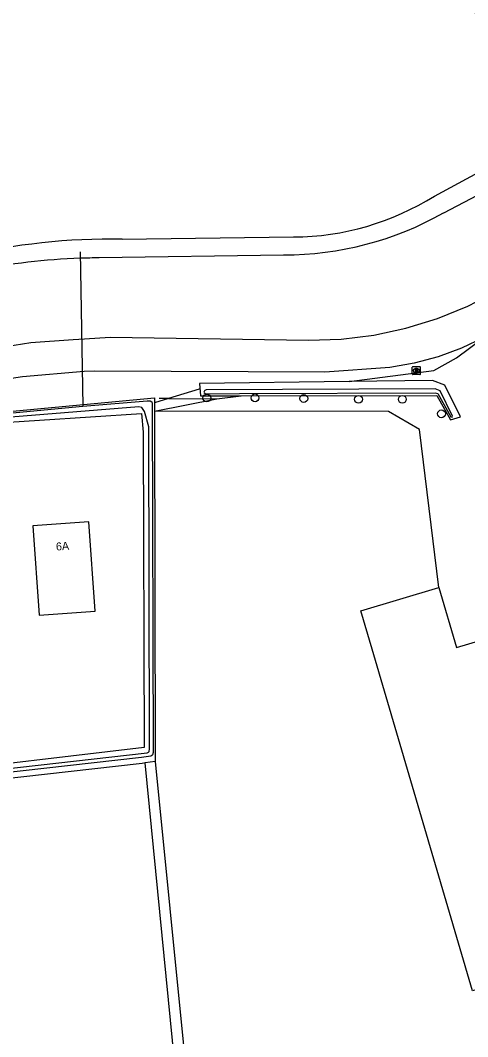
# Model space of a CAD drawing. Extents: x 161389 to 162585, y 388479 to 389761.
# Drawn here: x 162428.4 to 162484.3, y 389499.2 to 389626.2 of the extents above; entities that cross this region are included whole.
import ezdxf

# ---------------------------------------------------------------- set-up
doc = ezdxf.new("R2010")
doc.units = 0
for name, color, linetype in [('IMGEO_Boom', 7, 'Continuous'), ('IMGEO_Bouwland', 7, 'Continuous'), ('IMGEO_Duiker', 7, 'Continuous'), ('IMGEO_Erf', 7, 'Continuous'), ('IMGEO_Grasland_agrarisch', 7, 'Continuous'), ('IMGEO_Groenvoorziening', 7, 'Continuous'), ('IMGEO_Hek', 7, 'Continuous'), ('IMGEO_Pand', 7, 'Continuous'), ('IMGEO_Pand_nummerreeks', 7, 'Continuous'), ('IMGEO_Rijbaan_lokaal_gesloten', 7, 'Continuous'), ('IMGEO_Rioolput', 7, 'Continuous'), ('IMGEO_Waterloop', 7, 'Continuous')]:
    doc.layers.add(name, color=color, linetype=linetype)

msp = doc.modelspace()

# ---------------------------------------------------------------- linework, layer by layer
at = {"layer": 'IMGEO_Boom'}
for centre in [(162451.68, 389579.01), (162457.71, 389579.03), (162463.8, 389578.95), (162470.64, 389578.85), (162476.12, 389578.85), (162481, 389577.04)]:
    msp.add_circle(centre, 0.489, dxfattribs=at)
at = {"layer": 'IMGEO_Bouwland'}
msp.add_lwpolyline([(162444, 389533.43), (162443.61, 389533.38), (162386.27, 389526.91), (162383.3, 389558.74), (162372.05, 389554.21), (162367.03, 389552.01), (162329.55, 389533.6), (162286.17, 389511.67), (162288.77, 389500)], dxfattribs=at)
at = {"layer": 'IMGEO_Duiker'}
for points in [[(162435.87, 389597.28), (162436.21, 389577.98)], [(162450.71, 389580.1), (162446.89, 389578.94), (162445.16, 389578.42)]]:
    msp.add_lwpolyline(points, dxfattribs=at)
at = {"layer": 'IMGEO_Erf'}
for points in [[(162455.97, 389579.29), (162480.41, 389579.32), (162482.13, 389576.3), (162483.39, 389576.66), (162481.41, 389580.62), (162479.9, 389581.19), (162469.45, 389581.06)], [(162424.34, 389576.27), (162424.38, 389575.83), (162443.51, 389577.06), (162443.75, 389574.74), (162443.86, 389535.38), (162387.43, 389528.69), (162384.87, 389559.37), (162385.64, 389559.68)]]:
    msp.add_lwpolyline(points, dxfattribs=at)
at = {"layer": 'IMGEO_Grasland_agrarisch'}
for points in [[(162480.68, 389555.34), (162478.24, 389575.07), (162474.4, 389577.31), (162445.16, 389577.38)], [(162445.16, 389577.38), (162445.25, 389533.62)]]:
    msp.add_lwpolyline(points, dxfattribs=at)
at = {"layer": 'IMGEO_Groenvoorziening'}
for points in [[(162469.45, 389581.06), (162480.04, 389582.45), (162482.87, 389584.04), (162486.29, 389586.56)], [(162469.45, 389581.06), (162450.79, 389580.83), (162450.89, 389579.28), (162455.97, 389579.29)], [(162445.16, 389577.38), (162452.93, 389578.89), (162455.97, 389579.29)], [(162424.34, 389576.27), (162424.27, 389577.08), (162436.27, 389578.21), (162445.15, 389579.04), (162445.16, 389578.42), (162445.16, 389577.38)]]:
    msp.add_lwpolyline(points, dxfattribs=at)
at = {"layer": 'IMGEO_Hek'}
for points in [[(162446.89, 389578.94), (162445.71, 389578.95)], [(162446.89, 389578.94), (162447.29, 389578.94), (162452.93, 389578.89)]]:
    msp.add_lwpolyline(points, dxfattribs=at)
at = {"layer": 'IMGEO_Pand'}
for points in [[(162430.74, 389551.88), (162437.73, 389552.41), (162436.93, 389563.53), (162429.95, 389563.03), (162430.74, 389551.88)], [(162489.92, 389524.02), (162494.62, 389507.86), (162484.86, 389504.99), (162472.34, 389547.63), (162470.93, 389552.43), (162480.68, 389555.34)], [(162480.68, 389555.34), (162482.86, 389547.84), (162485.96, 389548.75), (162487.36, 389543.95), (162489.21, 389537.58)]]:
    msp.add_lwpolyline(points, dxfattribs=at)
at = {"layer": 'IMGEO_Rijbaan_lokaal_gesloten'}
for points in [[(162409.99, 389580.12), (162414.31, 389582.07), (162419.32, 389583.82), (162424.45, 389585.12), (162429.69, 389585.96), (162434.97, 389586.33), (162436.42, 389586.41), (162439.61, 389586.6), (162464.37, 389586.25), (162468.48, 389586.38), (162472.56, 389586.87), (162476.57, 389587.73), (162480.5, 389588.94), (162484.3, 389590.5), (162487.68, 389592.23), (162496.5, 389597.2)], [(162486.29, 389586.56), (162483.49, 389585.23), (162480.58, 389584.16), (162477.59, 389583.35), (162474.54, 389582.82), (162466.41, 389582.22), (162437.67, 389582.37), (162436.35, 389582.33), (162428.65, 389581.67), (162425.62, 389581.21), (162425.12, 389580.99)]]:
    msp.add_lwpolyline(points, dxfattribs=at)
at = {"layer": 'IMGEO_Rioolput'}
for p, q in [((162477.36, 389582.01), (162477.36, 389582.86)), ((162477.44, 389582.94), (162478.29, 389582.94)), ((162478.29, 389581.93), (162477.44, 389581.93)), ((162477.85, 389582.71), (162477.88, 389582.71)), ((162477.87, 389582.16), (162477.85, 389582.16)), ((162478.36, 389582.86), (162478.36, 389582.01))]:
    msp.add_line(p, q, dxfattribs=at)
for points in [[(162477.36, 389582.01), (162477.36, 389582.86)], [(162477.44, 389582.94), (162478.29, 389582.94)], [(162478.29, 389581.93), (162477.44, 389581.93)], [(162477.95, 389582.63), (162477.7, 389582.63), (162477.7, 389582.23)], [(162477.7, 389582.23), (162477.82, 389582.23), (162477.82, 389582.4), (162477.84, 389582.4)], [(162477.88, 389582.55), (162477.82, 389582.55), (162477.82, 389582.47)], [(162477.82, 389582.47), (162477.88, 389582.47)], [(162477.88, 389582.37), (162477.95, 389582.23), (162478.09, 389582.23), (162478.03, 389582.36)], [(162478.36, 389582.86), (162478.36, 389582.01)]]:
    msp.add_lwpolyline(points, dxfattribs=at)
for centre, radius, start, end in [((162477.44, 389582.86), 0.0765, 91.552, 178.448), ((162477.44, 389582.86), 0.0765, 91.552, 178.448), ((162477.44, 389582.01), 0.0765, 181.552, 268.448), ((162477.44, 389582.01), 0.0765, 181.552, 268.448), ((162477.83, 389582.34), 0.0533, 26.0293, 88.6989), ((162477.88, 389582.46), 0.0964, 77.0061, 93.1865), ((162477.86, 389582.66), 0.19, 274.7715, 282.9687), ((162477.9, 389582.51), 0.0378, 276.6634, 79.6772), ((162477.95, 389582.52), 0.109, 350.3612, 89.416), ((162477.95, 389582.52), 0.112, 277.5842, 350.9817), ((162477.93, 389582.31), 0.108, 29.5134, 73.7905), ((162478.29, 389582.86), 0.0765, 1.552, 88.448), ((162478.29, 389582.86), 0.0765, 1.552, 88.448), ((162478.29, 389582.01), 0.0765, 271.552, 358.448), ((162478.29, 389582.01), 0.0765, 271.552, 358.448)]:
    msp.add_arc(centre, radius, start, end, dxfattribs=at)
for centre, major_axis, ratio, start_param, end_param in [((162477.85, 389582.43), (-0.387, 0.002), 0.722429, 4.712389, 7.853982), ((162477.87, 389582.43), (-0.39, 0.002), 0.717154, 1.570796, 4.712389)]:
    msp.add_ellipse(centre, major_axis=major_axis, ratio=ratio, start_param=start_param, end_param=end_param, dxfattribs=at)
at = {"layer": 'IMGEO_Waterloop'}
for points in [[(162480.12, 389604.24), (162496.19, 389612.91), (162481.08, 389632.53), (162456.22, 389661.77), (162455.16, 389662.82), (162449.46, 389669.13), (162445.05, 389674.92), (162440.48, 389682.07), (162436.57, 389689.6)], [(162457.73, 389662.99), (162482.44, 389633.29), (162495.86, 389616), (162501.86, 389608.05), (162500.82, 389607.06), (162500.28, 389606.55), (162496.89, 389610.48), (162485.48, 389604.32), (162481.25, 389602.12)], [(162441.11, 389598.85), (162462.52, 389599.13)], [(162461.27, 389596.87), (162438.23, 389596.51)], [(162451.6, 389580.02), (162451.45, 389579.96), (162451.39, 389579.92), (162451.34, 389579.84), (162451.33, 389579.73)], [(162451.55, 389579.55), (162455.77, 389579.56), (162480.2, 389579.67), (162480.53, 389579.59), (162482.19, 389576.67), (162482.32, 389576.62), (162482.33, 389576.63), (162482.4, 389576.73), (162480.82, 389579.91), (162480.21, 389580.14), (162451.6, 389580.02)], [(162426.12, 389577.04), (162436.21, 389577.98), (162444.23, 389578.66), (162444.62, 389578.65), (162444.8, 389578.54), (162444.87, 389578.35), (162444.97, 389534.73), (162444.9, 389534.44), (162444.82, 389534.35), (162444.67, 389534.27), (162443.52, 389534.11), (162386.94, 389527.73), (162386.76, 389527.77), (162386.71, 389527.79), (162386.64, 389527.98), (162384.12, 389558.99), (162384.08, 389559.12), (162384, 389559.15), (162383.92, 389559.14), (162383.78, 389559.11), (162371.91, 389554.33), (162366.87, 389552.12), (162329.37, 389533.71), (162286.3, 389512.27)], [(162387.51, 389528.29), (162444.22, 389534.71), (162444.41, 389534.78), (162444.46, 389534.88), (162444.51, 389535.18), (162444.43, 389575.42), (162443.91, 389577.33), (162443.58, 389577.82), (162443.18, 389577.89), (162426.16, 389576.54)], [(162445.25, 389533.62), (162444, 389533.43)], [(162445.25, 389533.62), (162454.37, 389442.24)], [(162452.92, 389442.51), (162444, 389533.43)]]:
    msp.add_lwpolyline(points, dxfattribs=at)
for centre, radius, start, end in [((162462.47, 389632.19), 33.05, 270.0786, 302.2632), ((162461.3, 389637.4), 40.52, 269.9589, 299.4901), ((162439.59, 389520.52), 78.34, 88.8894, 118.2652), ((162438.58, 389517.78), 78.73, 91.9602, 111.0883), ((162438.61, 389515.64), 80.87, 90.2701, 91.9305), ((162451.62, 389579.87), 0.326, 207.0944, 258.4359)]:
    msp.add_arc(centre, radius, start, end, dxfattribs=at)

# ---------------------------------------------------------------- texts
at = {"layer": 'IMGEO_Pand_nummerreeks'}
msp.add_text('6A', height=1, rotation=4.099, dxfattribs=at).set_placement((162432.87, 389559.95))

doc.saveas('drawing.dxf')
